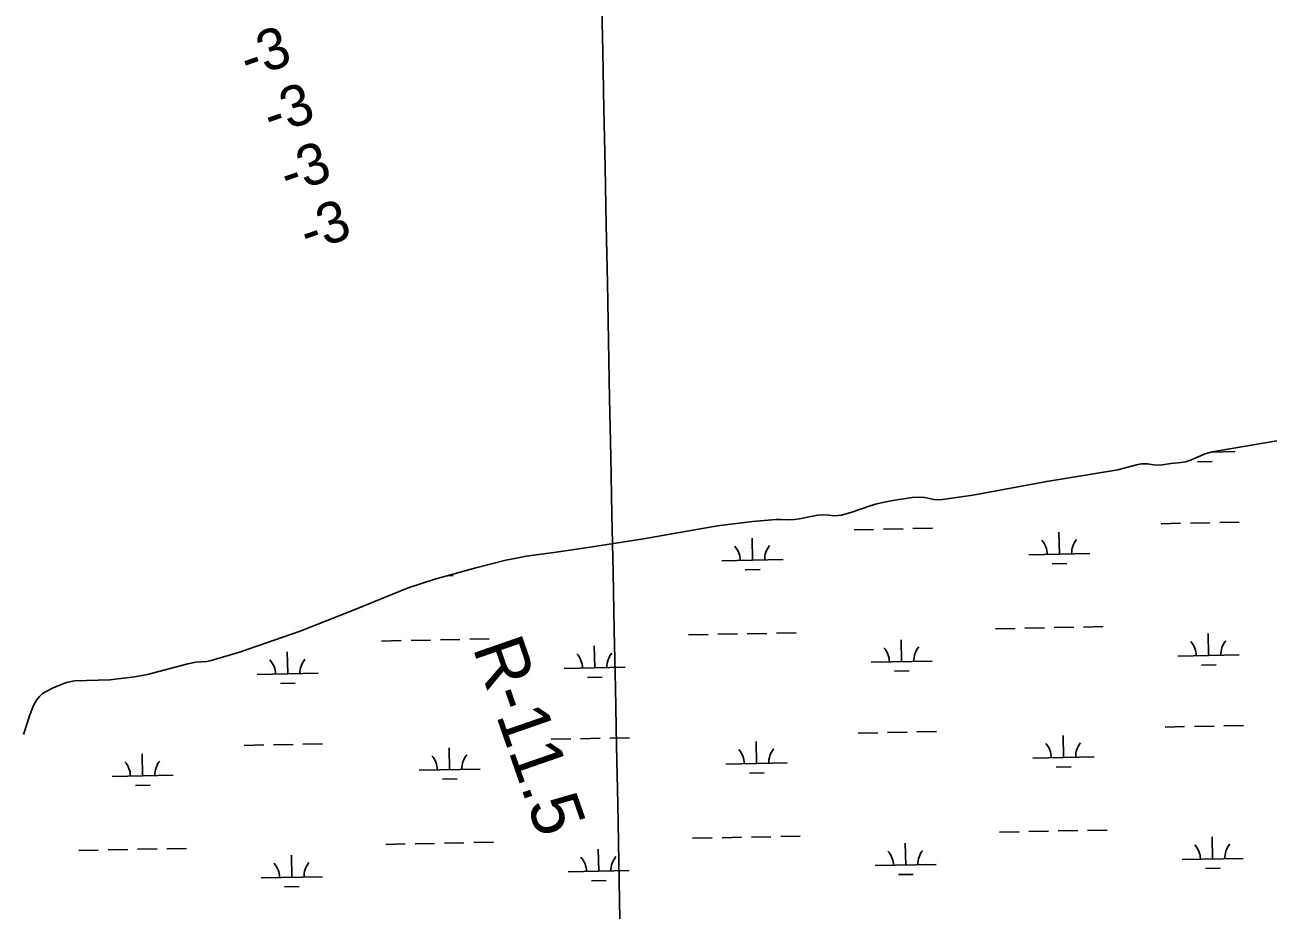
# Model space of a CAD drawing. Extents: x 3989314 to 4027622, y 243956 to 270014.
# Drawn here: x 4003151 to 4005183, y 256153 to 257601 of the extents above; entities that cross this region are included whole.
import ezdxf

# ---------------------------------------------------------------- set-up
doc = ezdxf.new("R2010")
doc.units = 0
for name, color, linetype in [('V-GRID-MAJR', 7, 'Continuous'), ('V-RIVR-EDGE', 7, 'Continuous'), ('V-RIVR-RANG', 7, 'Continuous'), ('V-RIVR-RANG-IDEN', 7, 'Continuous'), ('V-TOPO-SHOR', 7, 'Continuous'), ('V-WETL-SWMP', 7, 'Continuous')]:
    doc.layers.add(name, color=color, linetype=linetype)

msp = doc.modelspace()

# ---------------------------------------------------------------- linework, layer by layer
at = {"layer": 'V-GRID-MAJR'}
msp.add_spline([(4004252.853, 249607.957), (4004133.032, 255664.571), (4004013.15, 261724.27000000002), (4003893.269, 267783.95900000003), (4003893.208, 267787.051)], degree=3, dxfattribs=at)
at = {"layer": 'V-RIVR-EDGE'}
for points in [[(4003888.281, 256713.2), (4003937.19, 256725.714), (4003954.526, 256729.324), (4003970.181, 256732.288), (4004015.72, 256738.467), (4004067.7290000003, 256746.063), (4004162.046, 256760.874), (4004283.273, 256782.263), (4004340.324, 256788.95), (4004378.23, 256792.157), (4004387.0270000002, 256792.151), (4004398.4110000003, 256791.885), (4004408.7600000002, 256792.394), (4004417.04, 256793.68300000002), (4004438.517, 256798.065), (4004447.056, 256799.483), (4004455.207, 256799.995), (4004465.295, 256799.47), (4004473.186, 256798.43), (4004480.1720000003, 256798.684), (4004486.123, 256799.714), (4004502.556, 256804.619), (4004532.8340000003, 256814.816), (4004543.703, 256818.044), (4004553.664, 256820.364), (4004567.251, 256822.942), (4004579.93, 256825.134), (4004590.926, 256826.807), (4004601.276, 256828.093), (4004611.238, 256828.992), (4004621.455, 256828.081), (4004637.495, 256824.964), (4004643.8340000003, 256824.313), (4004650.948, 256825.085), (4004700.3710000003, 256832.423), (4004821.469, 256854.717), (4004937.779, 256873.524), (4004960.1610000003, 256879.58800000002), (4004967.9250000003, 256882.04200000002), (4004976.076, 256883.459), (4004986.038, 256883.193), (4004996.126, 256881.763), (4005006.733, 256881.36800000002), (4005024.327, 256883.813), (4005041.2770000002, 256885.611), (4005048.133, 256886.901), (4005056.284, 256889.611), (4005080.352, 256899.556), (4005091.739, 256902.911), (4005204.2970000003, 256922.238)], [(4003179.751, 256507.491), (4003184.539, 256510.592), (4003196.833, 256516.793), (4003203.821, 256519.763), (4003218.96, 256525.704), (4003231.77, 256528.411), (4003290.114, 256530.181), (4003298.265, 256530.953), (4003307.579, 256532.239), (4003326.079, 256534.295), (4003333.0640000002, 256535.325), (4003342.123, 256537.00100000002), (4003351.308, 256538.934), (4003406.944, 256553.514), (4003417.0360000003, 256556.352), (4003430.103, 256558.802), (4003448.215, 256560.21300000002), (4003455.588, 256561.888), (4003501.781, 256575.182), (4003600.896, 256609.651), (4003689.144, 256644.39), (4003777.654, 256680.547), (4003820.8710000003, 256695.008), (4003837.044, 256699.135), (4003888.281, 256713.2)]]:
    msp.add_lwpolyline(points, dxfattribs=at)
at = {"layer": 'V-TOPO-SHOR'}
msp.add_lwpolyline([(4003179.751, 256507.491), (4003174.8340000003, 256502.709), (4003169.7830000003, 256496.76), (4003165.12, 256488.226), (4003162.14, 256480.984), (4003158.38, 256471.024), (4003155.4, 256462.359), (4003148.398, 256440.503)], dxfattribs=at)
at = {"layer": 'V-WETL-SWMP'}
for p, q in [((4005090.7090199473, 256902.60750596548), (4005129.3085005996, 256903.37675581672)), ((4005067.6282727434, 256886.71346524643), (4005091.623508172, 256887.19166679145)), ((4004506.4166307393, 256775.5082102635), (4004538.4102779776, 256776.14581232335)), ((4004554.4071015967, 256776.46461335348), (4004586.4007488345, 256777.1022154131)), ((4004602.397572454, 256777.42101644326), (4004634.3912196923, 256778.05861850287)), ((4005008.224990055, 256785.50875947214), (4005040.2186372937, 256786.14636153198)), ((4005056.215460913, 256786.46516256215), (4005088.209108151, 256787.10276462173)), ((4005104.2059317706, 256787.4215656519), (4005136.199579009, 256788.0591677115)), ((4004340.310917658, 256725.7586667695), (4004339.593615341, 256761.75151991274)), ((4004842.1192769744, 256735.75921597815), (4004841.401974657, 256771.75206912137)), ((4004792.129203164, 256734.7629627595), (4004892.109350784, 256736.75546919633)), ((4004290.3208438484, 256724.76241355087), (4004390.300991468, 256726.7549199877)), ((4004830.429122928, 256720.0921786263), (4004854.4243583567, 256720.57038017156)), ((4003841.600475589, 256700.3857919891), (4003850.807639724, 256700.5692817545)), ((4004328.620763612, 256710.09162941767), (4004352.6159990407, 256710.5698309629)), ((4004737.6889104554, 256613.58317935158), (4004769.6825576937, 256614.22078141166)), ((4004785.679381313, 256614.53958244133), (4004817.673028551, 256615.1771845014)), ((4004833.66985217, 256615.49598553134), (4004865.663499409, 256616.13358759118)), ((4004881.6603230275, 256616.4523886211), (4004913.653970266, 256617.08999068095)), ((4003734.0721918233, 256593.58208093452), (4003766.0658390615, 256594.21968299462)), ((4003782.0626626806, 256594.5384840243), (4003814.056309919, 256595.17608608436)), ((4003830.0531335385, 256595.4948871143), (4003862.0467807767, 256596.13248917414)), ((4003878.043604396, 256596.45129020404), (4003910.037251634, 256597.08889226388)), ((4004235.880551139, 256603.58263014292), (4004267.8741983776, 256604.22023220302)), ((4004283.8710219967, 256604.5390332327), (4004315.8646692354, 256605.17663529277)), ((4004331.861492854, 256605.4954363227), (4004363.855140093, 256606.13303838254)), ((4004379.851963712, 256606.45183941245), (4004411.8456109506, 256607.0894414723)), ((4004584.1386382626, 256559.7709972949), (4004583.421335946, 256595.76385043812)), ((4005085.946997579, 256569.77154650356), (4005085.229695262, 256605.76439964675)), ((4003580.521919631, 256539.7698988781), (4003579.8046173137, 256575.7627520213)), ((4004082.330278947, 256549.7704480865), (4004081.6129766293, 256585.76330122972)), ((4005035.956923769, 256568.7752932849), (4005135.937071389, 256570.7677997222)), ((4004032.340205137, 256548.77419486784), (4004132.320352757, 256550.76670130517)), ((4004534.1485644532, 256558.77474407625), (4004634.1287120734, 256560.76725051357)), ((4005074.256843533, 256554.10450915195), (4005098.2520789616, 256554.58271069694)), ((4003530.531845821, 256538.77364565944), (4003630.511993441, 256540.76615209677)), ((4004070.6401249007, 256534.1034107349), (4004094.63536033, 256534.5816122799)), ((4004572.448484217, 256544.1039599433), (4004596.4437196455, 256544.5821614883)), ((4003568.831765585, 256524.10286152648), (4003592.8270010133, 256524.5810630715)), ((4005014.8535608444, 256452.89980337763), (4005046.847208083, 256453.53740543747)), ((4005062.8440317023, 256453.85620646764), (4005094.837678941, 256454.49380852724)), ((4005110.8345025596, 256454.81260955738), (4005142.8281497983, 256455.450211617)), ((4004011.2368422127, 256432.8987049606), (4004043.230489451, 256433.53630702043)), ((4004059.2273130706, 256433.8551080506), (4004091.2209603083, 256434.49271011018)), ((4004107.2177839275, 256434.81151114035), (4004139.2114311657, 256435.44911319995)), ((4004346.9394884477, 256393.149710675), (4004346.2221861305, 256429.14256381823)), ((4004513.045201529, 256442.899254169), (4004545.0388487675, 256443.53685622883)), ((4004561.035672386, 256443.855657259), (4004593.0293196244, 256444.4932593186)), ((4004609.026143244, 256444.81206034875), (4004641.0197904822, 256445.44966240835)), ((4004848.7478477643, 256403.15025988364), (4004848.0305454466, 256439.14311302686)), ((4003343.3227698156, 256373.1486122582), (4003342.605467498, 256409.14146540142)), ((4003509.428482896, 256422.8981557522), (4003541.422130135, 256423.53575781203)), ((4003557.418953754, 256423.8545588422), (4003589.4126009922, 256424.49216090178)), ((4003605.4094246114, 256424.81096193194), (4003637.40307185, 256425.44856399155)), ((4003845.131129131, 256383.1491614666), (4003844.4138268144, 256419.14201460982)), ((4004296.949414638, 256392.15345745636), (4004396.929562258, 256394.14596389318)), ((4004798.757773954, 256402.154006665), (4004898.7379215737, 256404.14651310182)), ((4004837.057693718, 256387.4832225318), (4004861.0529291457, 256387.96142407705)), ((4003293.3326960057, 256372.15235903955), (4003393.312843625, 256374.14486547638)), ((4003795.141055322, 256382.15290824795), (4003895.1212029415, 256384.14541468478)), ((4003833.4409750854, 256367.48212411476), (4003857.436210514, 256367.96032566)), ((4004335.249334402, 256377.48267332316), (4004359.24456983, 256377.9608748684)), ((4003331.6326157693, 256357.48157490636), (4003355.627851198, 256357.9597764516)), ((4004242.509121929, 256270.97367404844), (4004274.502769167, 256271.6112761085)), ((4004290.499592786, 256271.93007713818), (4004322.4932400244, 256272.56767919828)), ((4004338.4900636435, 256272.8864802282), (4004370.4837108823, 256273.52408228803)), ((4004386.4805345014, 256273.84288331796), (4004418.47418174, 256274.4804853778)), ((4004744.317481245, 256280.97422325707), (4004776.3111284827, 256281.61182531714)), ((4004792.3079521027, 256281.93062634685), (4004824.3015993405, 256282.56822840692)), ((4004840.29842296, 256282.88702943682), (4004872.2920701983, 256283.52463149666)), ((4004888.2888938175, 256283.8434325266), (4004920.2825410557, 256284.48103458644)), ((4005092.575568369, 256237.16259040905), (4005091.8582660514, 256273.15544355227)), ((4003238.8924032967, 256250.97257563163), (4003270.886050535, 256251.6101776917)), ((4003286.882874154, 256251.92897872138), (4003318.8765213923, 256252.56658078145)), ((4003334.873345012, 256252.8853818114), (4003366.86699225, 256253.52298387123)), ((4003382.863815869, 256253.84178490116), (4003414.8574631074, 256254.479386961)), ((4003740.7007626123, 256260.97312484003), (4003772.694409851, 256261.6107269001)), ((4003788.69123347, 256261.92952792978), (4003820.684880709, 256262.56712998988)), ((4003836.6817043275, 256262.8859310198), (4003868.675351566, 256263.52353307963)), ((4003884.6721751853, 256263.84233410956), (4003916.665822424, 256264.4799361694)), ((4004088.9588497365, 256217.161491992), (4004088.241547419, 256253.1543451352)), ((4004590.7672090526, 256227.1620412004), (4004590.0499067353, 256263.1548943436)), ((4003587.1504904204, 256207.1609427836), (4003586.4331881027, 256243.1537959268)), ((4004540.7771352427, 256226.16578798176), (4004640.757282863, 256228.15829441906)), ((4005042.585494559, 256236.1663371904), (4005142.5656421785, 256238.1588436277)), ((4003537.160416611, 256206.16468956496), (4003637.1405642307, 256208.15719600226)), ((4004038.9687759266, 256216.16523877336), (4004138.948923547, 256218.15774521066)), ((4004579.0770550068, 256211.4950038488), (4004603.072290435, 256211.9732053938)), ((4005080.885414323, 256221.49555305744), (4005104.880649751, 256221.97375460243)), ((4003575.4603363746, 256191.493905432), (4003599.4555718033, 256191.972106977)), ((4004077.26869569, 256201.4944546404), (4004101.263931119, 256201.9726561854))]:
    msp.add_line(p, q, dxfattribs=at)
for points in [[(4003954.526, 256729.324), (4003970.181, 256732.288), (4004015.721, 256738.46600000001), (4004067.7290000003, 256746.062), (4004162.045, 256760.873), (4004283.272, 256782.263), (4004340.325, 256788.95), (4004378.23, 256792.157), (4004387.0270000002, 256792.151), (4004398.4110000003, 256791.885), (4004408.7600000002, 256792.39500000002), (4004417.04, 256793.68300000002), (4004438.517, 256798.066), (4004447.056, 256799.483), (4004455.2060000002, 256799.995), (4004465.296, 256799.47), (4004473.187, 256798.43), (4004480.1720000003, 256798.684), (4004486.1240000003, 256799.715), (4004502.556, 256804.619), (4004532.8340000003, 256814.817), (4004543.702, 256818.044), (4004553.665, 256820.36500000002), (4004567.25, 256822.943), (4004579.929, 256825.133), (4004590.926, 256826.80800000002), (4004601.276, 256828.094), (4004611.237, 256828.99300000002), (4004621.4560000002, 256828.08000000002), (4004637.495, 256824.964), (4004643.833, 256824.313), (4004650.949, 256825.084), (4004700.37, 256832.423), (4004821.468, 256854.718), (4004937.778, 256873.524), (4004960.162, 256879.589), (4004967.9250000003, 256882.041), (4004976.076, 256883.458), (4004986.037, 256883.193), (4004996.126, 256881.763), (4005006.733, 256881.367), (4005024.328, 256883.813), (4005041.276, 256885.612), (4005048.133, 256886.901), (4005056.285, 256889.612), (4005080.353, 256899.556), (4005091.739, 256902.911), (4005204.298, 256922.237)], [(4003148.399, 256440.503), (4003155.4, 256462.36000000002), (4003158.381, 256471.025), (4003162.14, 256480.984), (4003165.12, 256488.226), (4003169.7830000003, 256496.76), (4003174.833, 256502.708), (4003179.752, 256507.491), (4003184.54, 256510.592), (4003196.8340000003, 256516.793), (4003203.822, 256519.763), (4003218.961, 256525.703), (4003231.77, 256528.411), (4003290.113, 256530.181), (4003298.264, 256530.95200000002), (4003307.579, 256532.239), (4003326.079, 256534.296), (4003333.065, 256535.326), (4003342.122, 256537.00100000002), (4003351.308, 256538.935), (4003406.943, 256553.514), (4003417.0360000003, 256556.353), (4003430.103, 256558.802), (4003448.215, 256560.21300000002), (4003455.589, 256561.889), (4003501.781, 256575.181), (4003600.896, 256609.652), (4003689.145, 256644.389), (4003777.654, 256680.548), (4003820.8710000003, 256695.007), (4003837.044, 256699.135), (4003888.281, 256713.2), (4003937.1890000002, 256725.714), (4003954.526, 256729.324)]]:
    msp.add_lwpolyline(points, dxfattribs=at)
for centre, radius, start, end in [((4005134.54093537, 256903.9559305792), 35.246287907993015, 179.58953041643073, 181.91353291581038), ((4004786.877847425, 256735.13320584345), 35.24628790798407, 0.3698775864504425, 41.913535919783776), ((4004897.341785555, 256737.3346439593), 35.246287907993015, 140.36987458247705, 181.91353291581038), ((4004285.0694881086, 256725.1326566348), 35.24628790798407, 0.3698775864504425, 41.913535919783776), ((4004395.5334262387, 256727.33409475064), 35.246287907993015, 140.36987458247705, 181.91353291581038), ((4005030.7055680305, 256569.1455363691), 35.24628790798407, 0.3698775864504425, 41.913535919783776), ((4005141.16950616, 256571.34697448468), 35.246287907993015, 140.36987458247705, 181.91353291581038), ((4004027.0888493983, 256549.14443795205), 35.24628790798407, 0.3698775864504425, 41.913535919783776), ((4004137.5527875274, 256551.34587606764), 35.246287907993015, 140.36987458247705, 181.91353291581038), ((4004528.8972087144, 256559.14498716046), 35.24628790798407, 0.3698775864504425, 41.913535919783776), ((4004639.361146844, 256561.34642527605), 35.246287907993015, 140.36987458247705, 181.91353291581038), ((4003525.2804900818, 256539.14388874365), 35.24628790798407, 0.3698775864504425, 41.913535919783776), ((4003635.7444282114, 256541.34532685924), 35.246287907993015, 140.36987458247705, 181.91353291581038), ((4004291.6980588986, 256392.5237005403), 35.24628790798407, 0.3698775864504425, 41.913535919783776), ((4004402.1619970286, 256394.72513865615), 35.246287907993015, 140.36987458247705, 181.91353291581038), ((4004793.506418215, 256402.52424974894), 35.24628790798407, 0.3698775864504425, 41.913535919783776), ((4004903.9703563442, 256404.7256878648), 35.246287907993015, 140.36987458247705, 181.91353291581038), ((4003288.0813402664, 256372.5226021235), 35.24628790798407, 0.3698775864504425, 41.913535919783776), ((4003398.5452783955, 256374.72404023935), 35.246287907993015, 140.36987458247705, 181.91353291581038), ((4003789.889699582, 256382.5231513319), 35.24628790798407, 0.3698775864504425, 41.913535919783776), ((4003900.353637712, 256384.72458944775), 35.246287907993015, 140.36987458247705, 181.91353291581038), ((4004535.525779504, 256226.53603106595), 35.24628790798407, 0.3698775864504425, 41.913535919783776), ((4004645.9897176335, 256228.73746918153), 35.246287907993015, 140.36987458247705, 181.91353291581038), ((4005037.33413882, 256236.53658027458), 35.24628790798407, 0.3698775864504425, 41.913535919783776), ((4005147.798076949, 256238.73801839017), 35.246287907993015, 140.36987458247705, 181.91353291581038), ((4003531.9090608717, 256206.53493264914), 35.24628790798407, 0.3698775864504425, 41.913535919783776), ((4003642.3729990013, 256208.73637076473), 35.246287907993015, 140.36987458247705, 181.91353291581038), ((4004033.7174201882, 256216.53548185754), 35.24628790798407, 0.3698775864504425, 41.913535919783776), ((4004144.1813583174, 256218.73691997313), 35.246287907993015, 140.36987458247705, 181.91353291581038)]:
    msp.add_arc(centre, radius, start, end, dxfattribs=at)

# ---------------------------------------------------------------- texts
at = {"layer": 'V-RIVR-RANG'}
for p in [(4003515.632675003, 257512.71945752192), (4003553.672675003, 257420.10945752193), (4003580.8326750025, 257323.97945752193), (4003613.3126750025, 257229.1494575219)]:
    msp.add_text('-3', height=67, rotation=19.127277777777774, dxfattribs=at).set_placement(p)
at = {"layer": 'V-RIVR-RANG-IDEN'}
msp.add_text('R-11.5', height=82.99999799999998, rotation=289.14123483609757, dxfattribs=at).set_placement((4003882.3061448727, 256582.9816340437))

doc.saveas('drawing.dxf')
